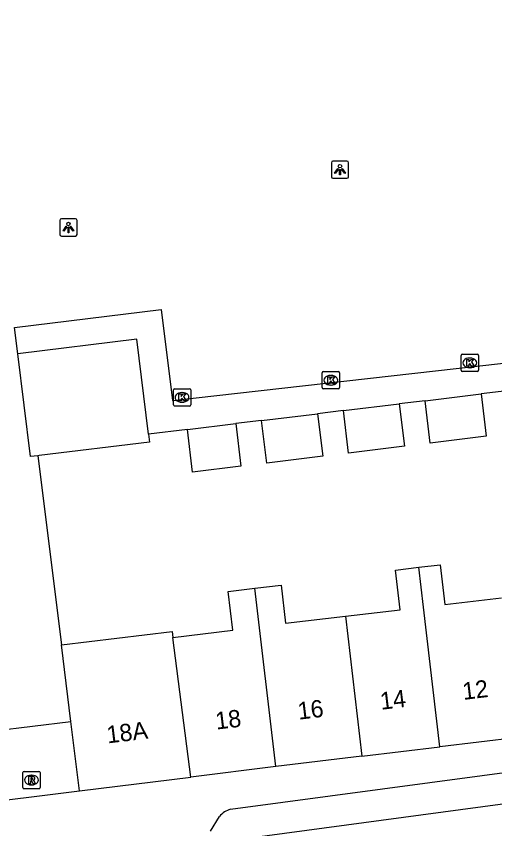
# Model space of a CAD drawing. Extents: x 162172 to 163187, y 382874 to 383684.
# Drawn here: x 162857.43 to 162885.02, y 383280.9 to 383327.79 of the extents above; entities that cross this region are included whole.
import ezdxf

# ---------------------------------------------------------------- set-up
doc = ezdxf.new("R2010")
doc.units = 0
for name, color, linetype in [('IMGEO_Hek', 7, 'Continuous'), ('IMGEO_Kolk', 7, 'Continuous'), ('IMGEO_Lichtpunt', 7, 'Continuous'), ('IMGEO_Pand', 7, 'Continuous'), ('IMGEO_Pand_nummerreeks', 7, 'Continuous'), ('IMGEO_Rijbaan_lokaal_gesloten', 7, 'Continuous'), ('IMGEO_Rijbaan_lokaal_open', 7, 'Continuous'), ('IMGEO_Rioolput', 7, 'Continuous'), ('IMGEO_Voetpad_open', 7, 'Continuous')]:
    doc.layers.add(name, color=color, linetype=linetype)

msp = doc.modelspace()

# ---------------------------------------------------------------- linework, layer by layer
at = {"layer": 'IMGEO_Hek'}
msp.add_lwpolyline([(162853.928, 383286.286), (162860.58, 383287.089)], dxfattribs=at)
at = {"layer": 'IMGEO_Kolk'}
for p, q in [((162883.161, 383308.286), (162884.013, 383308.286)), ((162883.086, 383307.36), (162883.086, 383308.212)), ((162883.574, 383308.066), (162883.599, 383308.066)), ((162884.087, 383308.212), (162884.087, 383307.36)), ((162883.597, 383307.506), (162883.572, 383307.506)), ((162875.069, 383306.357), (162875.069, 383307.209)), ((162875.144, 383307.283), (162875.996, 383307.283)), ((162875.557, 383307.063), (162875.582, 383307.063)), ((162876.07, 383307.209), (162876.07, 383306.357)), ((162884.013, 383307.286), (162883.161, 383307.286)), ((162875.58, 383306.503), (162875.555, 383306.503)), ((162866.487, 383305.367), (162866.487, 383306.219)), ((162866.562, 383306.293), (162867.414, 383306.293)), ((162866.975, 383306.073), (162867, 383306.073)), ((162867.488, 383306.219), (162867.488, 383305.367)), ((162875.996, 383306.283), (162875.144, 383306.283)), ((162866.998, 383305.513), (162866.973, 383305.513)), ((162867.414, 383305.293), (162866.562, 383305.293))]:
    msp.add_line(p, q, dxfattribs=at)
for points in [[(162883.161, 383308.286), (162884.013, 383308.286)], [(162883.086, 383307.36), (162883.086, 383308.212)], [(162883.407, 383307.986), (162883.53, 383307.986), (162883.53, 383307.835), (162883.66, 383307.986), (162883.824, 383307.986), (162883.678, 383307.835), (162883.831, 383307.586), (162883.679, 383307.586), (162883.594, 383307.75), (162883.53, 383307.683), (162883.53, 383307.586), (162883.407, 383307.586), (162883.407, 383307.986)], [(162884.087, 383308.212), (162884.087, 383307.36)], [(162875.069, 383306.357), (162875.069, 383307.209)], [(162875.144, 383307.283), (162875.996, 383307.283)], [(162875.39, 383306.983), (162875.513, 383306.983), (162875.513, 383306.832), (162875.643, 383306.983), (162875.807, 383306.983), (162875.661, 383306.832), (162875.814, 383306.583), (162875.662, 383306.583), (162875.577, 383306.747), (162875.513, 383306.68), (162875.513, 383306.583), (162875.39, 383306.583), (162875.39, 383306.983)], [(162876.07, 383307.209), (162876.07, 383306.357)], [(162884.013, 383307.286), (162883.161, 383307.286)], [(162866.487, 383305.367), (162866.487, 383306.219)], [(162866.562, 383306.293), (162867.414, 383306.293)], [(162866.808, 383305.993), (162866.931, 383305.993), (162866.931, 383305.842), (162867.061, 383305.993), (162867.225, 383305.993), (162867.079, 383305.842), (162867.232, 383305.593), (162867.08, 383305.593), (162866.995, 383305.757), (162866.931, 383305.69), (162866.931, 383305.593), (162866.808, 383305.593), (162866.808, 383305.993)], [(162867.488, 383306.219), (162867.488, 383305.367)], [(162875.996, 383306.283), (162875.144, 383306.283)], [(162867.414, 383305.293), (162866.562, 383305.293)]]:
    msp.add_lwpolyline(points, dxfattribs=at)
for centre, start, end in [((162883.163, 383308.21), 91.552, 178.448), ((162883.163, 383308.21), 91.552, 178.448), ((162884.011, 383308.21), 1.552, 88.448), ((162884.011, 383308.21), 1.552, 88.448), ((162883.163, 383307.362), 181.552, 268.448), ((162883.163, 383307.362), 181.552, 268.448), ((162884.011, 383307.362), 271.552, 358.448), ((162884.011, 383307.362), 271.552, 358.448), ((162875.146, 383307.207), 91.552, 178.448), ((162875.146, 383307.207), 91.552, 178.448), ((162875.994, 383307.207), 1.552, 88.448), ((162875.994, 383307.207), 1.552, 88.448), ((162866.564, 383306.217), 91.552, 178.448), ((162866.564, 383306.217), 91.552, 178.448), ((162867.412, 383306.217), 1.552, 88.448), ((162867.412, 383306.217), 1.552, 88.448), ((162875.146, 383306.359), 181.552, 268.448), ((162875.146, 383306.359), 181.552, 268.448), ((162875.994, 383306.359), 271.552, 358.448), ((162875.994, 383306.359), 271.552, 358.448), ((162866.564, 383305.369), 181.552, 268.448), ((162866.564, 383305.369), 181.552, 268.448), ((162867.412, 383305.369), 271.552, 358.448), ((162867.412, 383305.369), 271.552, 358.448)]:
    msp.add_arc(centre, 0.0765, start, end, dxfattribs=at)
for centre, major_axis, ratio, start_param, end_param in [((162883.573, 383307.786), (-0.387, 0.002), 0.722429, 4.712389, 7.853982), ((162883.598, 383307.786), (-0.39, 0.002), 0.717154, 1.570796, 4.712389), ((162875.556, 383306.783), (-0.387, 0.002), 0.722429, 4.712389, 7.853982), ((162875.581, 383306.783), (-0.39, 0.002), 0.717154, 1.570796, 4.712389), ((162866.974, 383305.793), (-0.387, 0.002), 0.722429, 4.712389, 7.853982), ((162866.999, 383305.793), (-0.39, 0.002), 0.717154, 1.570796, 4.712389)]:
    msp.add_ellipse(centre, major_axis=major_axis, ratio=ratio, start_param=start_param, end_param=end_param, dxfattribs=at)
at = {"layer": 'IMGEO_Lichtpunt'}
for p, q in [((162875.598, 383319.338), (162875.598, 383318.531)), ((162875.598, 383319.338), (162875.598, 383318.531)), ((162876.5, 383319.433), (162875.692, 383319.433)), ((162876.5, 383319.433), (162875.692, 383319.433)), ((162876.594, 383318.531), (162876.594, 383319.338)), ((162876.594, 383318.531), (162876.594, 383319.338)), ((162875.692, 383318.437), (162876.5, 383318.437)), ((162875.692, 383318.437), (162876.5, 383318.437)), ((162859.937, 383316.005), (162859.937, 383315.198)), ((162859.937, 383316.005), (162859.937, 383315.198)), ((162860.839, 383316.1), (162860.031, 383316.1)), ((162860.839, 383316.1), (162860.031, 383316.1)), ((162860.933, 383315.198), (162860.933, 383316.005)), ((162860.933, 383315.198), (162860.933, 383316.005)), ((162860.031, 383315.104), (162860.839, 383315.104)), ((162860.031, 383315.104), (162860.839, 383315.104))]:
    msp.add_line(p, q, dxfattribs=at)
for points in [[(162875.972, 383319.002), (162876.011, 383318.974), (162875.823, 383318.712), (162875.785, 383318.739), (162875.972, 383319.002)], [(162876.074, 383318.954), (162876.121, 383318.954), (162876.121, 383318.632), (162876.074, 383318.632), (162876.074, 383318.954)], [(162876.184, 383318.974), (162876.222, 383319.001), (162876.409, 383318.739), (162876.37, 383318.711), (162876.184, 383318.974)], [(162860.311, 383315.669), (162860.35, 383315.641), (162860.162, 383315.379), (162860.124, 383315.406), (162860.311, 383315.669)], [(162860.413, 383315.621), (162860.46, 383315.621), (162860.46, 383315.299), (162860.413, 383315.299), (162860.413, 383315.621)], [(162860.523, 383315.641), (162860.561, 383315.668), (162860.748, 383315.406), (162860.709, 383315.378), (162860.523, 383315.641)]]:
    msp.add_lwpolyline(points, dxfattribs=at)
for centre in [(162876.097, 383319.136), (162860.436, 383315.803)]:
    msp.add_circle(centre, 0.0994, dxfattribs=at)
for centre, start, end in [((162875.692, 383319.338), 90, 180), ((162875.692, 383319.338), 90, 180), ((162876.5, 383319.338), 0, 90), ((162876.5, 383319.338), 0, 90), ((162875.692, 383318.531), 180, 270), ((162875.692, 383318.531), 180, 270), ((162876.5, 383318.531), 270, 0), ((162876.5, 383318.531), 270, 360), ((162860.031, 383316.005), 90, 180), ((162860.031, 383316.005), 90, 180), ((162860.839, 383316.005), 0, 90), ((162860.839, 383316.005), 0, 90), ((162860.031, 383315.198), 180, 270), ((162860.031, 383315.198), 180, 270), ((162860.839, 383315.198), 270, 0), ((162860.839, 383315.198), 270, 360)]:
    msp.add_arc(centre, 0.0946, start, end, dxfattribs=at)
at = {"layer": 'IMGEO_Pand'}
for points in [[(162865.06, 383303.671), (162865.06, 383303.675), (162864.39, 383309.157), (162857.521, 383308.31)], [(162858.676, 383302.426), (162858.253, 383302.375), (162857.521, 383308.31)], [(162884.234, 383305.992), (162884.533, 383303.55), (162881.304, 383303.154), (162881.004, 383305.602)], [(162881.004, 383305.602), (162884.234, 383305.992)], [(162879.511, 383305.421), (162879.811, 383302.971), (162876.596, 383302.577), (162876.295, 383305.032)], [(162876.295, 383305.032), (162879.511, 383305.421)], [(162874.798, 383304.851), (162875.1, 383302.393), (162871.876, 383301.998), (162871.574, 383304.461)], [(162871.574, 383304.461), (162874.798, 383304.851)], [(162870.085, 383304.281), (162870.387, 383301.815), (162867.598, 383301.473), (162867.299, 383303.945)], [(162867.299, 383303.945), (162870.085, 383304.281)], [(162865.06, 383303.671), (162865.118, 383303.202), (162858.745, 383302.434), (162858.676, 383302.426)], [(162880.641, 383295.985), (162881.881, 383296.131), (162882.151, 383293.837), (162885.413, 383294.22)], [(162876.41, 383293.162), (162879.567, 383293.533), (162879.298, 383295.828), (162880.641, 383295.985)], [(162881.856, 383285.629), (162880.91, 383293.691), (162880.641, 383295.985)], [(162866.456, 383291.94), (162869.923, 383292.363), (162869.651, 383294.589), (162871.189, 383294.777)], [(162871.189, 383294.777), (162872.701, 383294.955), (162872.959, 383292.757), (162876.41, 383293.162)], [(162872.396, 383284.492), (162871.189, 383294.777)], [(162876.41, 383293.162), (162877.358, 383285.088)], [(162860.03, 383291.52), (162866.417, 383292.272), (162866.456, 383291.94)], [(162867.493, 383283.866), (162866.456, 383291.94)], [(162861.078, 383283.082), (162860.58, 383287.089), (162860.03, 383291.52)], [(162886.358, 383286.17), (162881.856, 383285.629)], [(162877.358, 383285.088), (162881.856, 383285.629)], [(162877.358, 383285.088), (162872.396, 383284.492)], [(162872.396, 383284.492), (162867.493, 383283.866)], [(162861.078, 383283.082), (162867.493, 383283.866)]]:
    msp.add_lwpolyline(points, dxfattribs=at)
at = {"layer": 'IMGEO_Rijbaan_lokaal_gesloten'}
msp.add_lwpolyline([(162910.202, 383285.636), (162867.323, 383279.879)], dxfattribs=at)
at = {"layer": 'IMGEO_Rijbaan_lokaal_open'}
for points in [[(162857.521, 383308.31), (162857.334, 383309.83)], [(162858.676, 383302.426), (162860.03, 383291.52)], [(162854.418, 383282.266), (162861.078, 383283.082)]]:
    msp.add_lwpolyline(points, dxfattribs=at)
at = {"layer": 'IMGEO_Rioolput'}
for p, q in [((162857.802, 383283.282), (162857.802, 383284.134)), ((162857.877, 383284.208), (162858.729, 383284.208)), ((162858.29, 383283.988), (162858.315, 383283.988)), ((162858.803, 383284.134), (162858.803, 383283.282)), ((162858.313, 383283.428), (162858.288, 383283.428)), ((162858.729, 383283.208), (162857.877, 383283.208))]:
    msp.add_line(p, q, dxfattribs=at)
for points in [[(162857.802, 383283.282), (162857.802, 383284.134)], [(162857.877, 383284.208), (162858.729, 383284.208)], [(162858.391, 383283.906), (162858.139, 383283.908), (162858.139, 383283.508)], [(162858.803, 383284.134), (162858.803, 383283.282)], [(162858.139, 383283.508), (162858.263, 383283.508), (162858.263, 383283.67), (162858.274, 383283.67)], [(162858.317, 383283.827), (162858.263, 383283.827), (162858.263, 383283.746)], [(162858.263, 383283.746), (162858.315, 383283.746)], [(162858.321, 383283.641), (162858.392, 383283.508), (162858.532, 383283.508), (162858.467, 383283.634)], [(162858.729, 383283.208), (162857.877, 383283.208)]]:
    msp.add_lwpolyline(points, dxfattribs=at)
for centre, radius, start, end in [((162857.879, 383284.132), 0.0765, 91.552, 178.448), ((162857.879, 383284.132), 0.0765, 91.552, 178.448), ((162858.39, 383283.796), 0.109, 350.3612, 89.416), ((162858.727, 383284.132), 0.0765, 1.552, 88.448), ((162858.727, 383284.132), 0.0765, 1.552, 88.448), ((162858.273, 383283.617), 0.0533, 26.0293, 88.6989), ((162858.299, 383283.935), 0.19, 274.7715, 282.9687), ((162858.323, 383283.731), 0.0964, 77.0061, 93.1865), ((162858.337, 383283.788), 0.0378, 276.6634, 79.6772), ((162858.388, 383283.796), 0.112, 277.5842, 350.9817), ((162858.372, 383283.581), 0.108, 29.5134, 73.7905), ((162857.879, 383283.284), 0.0765, 181.552, 268.448), ((162857.879, 383283.284), 0.0765, 181.552, 268.448), ((162858.727, 383283.284), 0.0765, 271.552, 358.448), ((162858.727, 383283.284), 0.0765, 271.552, 358.448)]:
    msp.add_arc(centre, radius, start, end, dxfattribs=at)
for centre, major_axis, ratio, start_param, end_param in [((162858.289, 383283.708), (-0.387, 0.002), 0.722429, 4.712389, 7.853982), ((162858.314, 383283.708), (-0.39, 0.002), 0.717154, 1.570796, 4.712389)]:
    msp.add_ellipse(centre, major_axis=major_axis, ratio=ratio, start_param=start_param, end_param=end_param, dxfattribs=at)
at = {"layer": 'IMGEO_Voetpad_open'}
for points in [[(162857.334, 383309.83), (162865.781, 383310.872), (162866.43, 383305.611), (162891.656, 383308.468), (162894.87, 383308.939), (162900.797, 383313.985), (162901.094, 383314.238), (162895.162, 383320.942), (162856.135, 383364.326), (162860.348, 383368.115), (162857.54, 383371.237), (162798.204, 383318.046), (162815.123, 383299.172), (162815.965, 383299.314), (162828.499, 383300.83), (162843.549, 383302.649), (162843.706, 383302.686), (162843.036, 383308.139), (162851.601, 383309.192)], [(162885.724, 383306.172), (162884.234, 383305.992)], [(162881.004, 383305.602), (162879.511, 383305.421)], [(162876.295, 383305.032), (162874.798, 383304.851)], [(162871.574, 383304.461), (162870.085, 383304.281)], [(162867.299, 383303.945), (162865.06, 383303.671)], [(162869.786, 383282.025), (162907.28, 383287.053)], [(162868.622, 383280.753), (162869.141, 383281.604)]]:
    msp.add_lwpolyline(points, dxfattribs=at)
msp.add_arc((162870.149, 383280.765), 1.311, 106.053, 140.2131, dxfattribs=at)

# ---------------------------------------------------------------- texts
at = {"layer": 'IMGEO_Pand_nummerreeks'}
for s, rotation, p in [('12', 6.8526, (162883.218, 383288.33)), ('14', 6.8526, (162878.469, 383287.76)), ('16', 6.8533, (162873.718, 383287.189)), ('18', 6.8533, (162868.969, 383286.618)), ('18A', 6.9664, (162862.699, 383285.819))]:
    msp.add_text(s, height=1, rotation=rotation, dxfattribs=at).set_placement(p)

doc.saveas('drawing.dxf')
